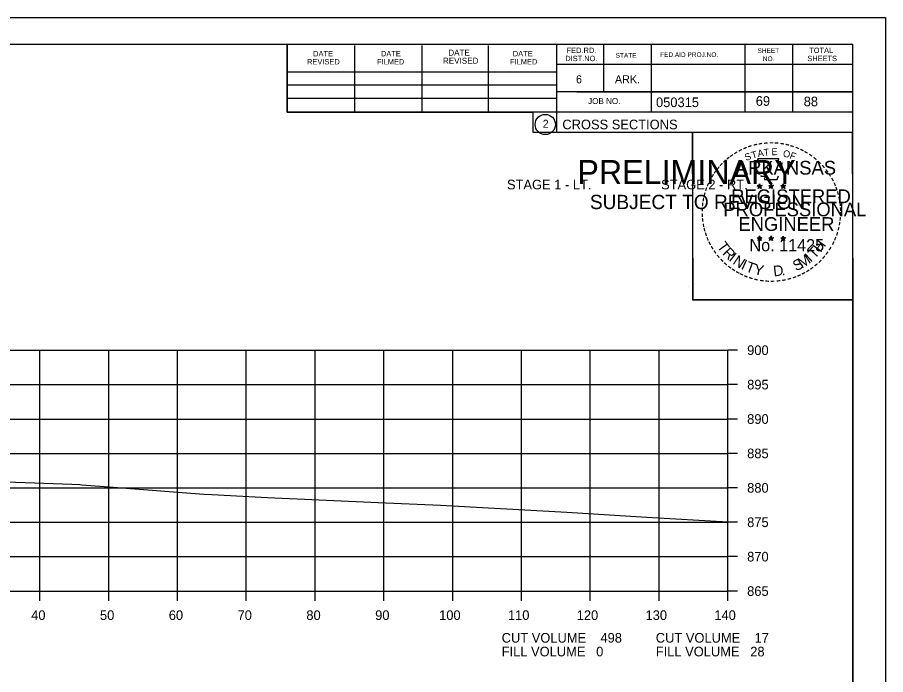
# Model space of a CAD drawing. Extents: x 1486524 to 1499135, y 326561 to 337924.
# Drawn here: x 1489019.6 to 1489145.8, y 332257.1 to 332352.6 of the extents above; entities that cross this region are included whole.
import ezdxf

# ---------------------------------------------------------------- set-up
doc = ezdxf.new("R2010")
doc.units = 0
for name, color, linetype in [('Default', 7, 'Continuous'), ('E_Const Align', 7, 'Continuous'), ('E_Const Align Station', 7, 'Continuous'), ('E_Ownership Information', 7, 'Continuous'), ('E_Property Line', 7, 'Continuous'), ('E_Quarter Calls', 7, 'Continuous'), ('E_Section Line', 7, 'Continuous'), ('E_Station Offset', 7, 'Continuous'), ('E_Tract Number', 7, 'Continuous'), ('S_SIXTEEN_SECTION', 7, 'Continuous')]:
    doc.layers.add(name, color=color, linetype=linetype)

msp = doc.modelspace()

# ---------------------------------------------------------------- linework, layer by layer
at = {"layer": 'E_Const Align'}
for p, q in [((1489122.89, 332269.27), (1489122.89, 332304.27)), ((1489124.29, 332304.27), (1489122.89, 332304.27)), ((1489124.29, 332299.27), (1489122.89, 332299.27)), ((1489124.29, 332294.27), (1489122.89, 332294.27)), ((1489124.29, 332289.27), (1489122.89, 332289.27)), ((1489124.29, 332284.27), (1489122.89, 332284.27)), ((1489124.29, 332279.27), (1489122.89, 332279.27)), ((1489124.29, 332274.27), (1489122.89, 332274.27)), ((1488842.89, 332269.27), (1489122.89, 332269.27)), ((1489022.89, 332267.87), (1489022.89, 332269.27)), ((1489032.89, 332267.87), (1489032.89, 332269.27)), ((1489042.89, 332267.87), (1489042.89, 332269.27)), ((1489052.89, 332267.87), (1489052.89, 332269.27)), ((1489062.89, 332267.87), (1489062.89, 332269.27)), ((1489072.89, 332267.87), (1489072.89, 332269.27)), ((1489082.89, 332267.87), (1489082.89, 332269.27)), ((1489092.89, 332267.87), (1489092.89, 332269.27)), ((1489102.89, 332267.87), (1489102.89, 332269.27)), ((1489112.89, 332267.87), (1489112.89, 332269.27)), ((1489122.89, 332267.87), (1489122.89, 332269.27)), ((1489124.29, 332269.27), (1489122.89, 332269.27))]:
    msp.add_line(p, q, dxfattribs=at)
at = {"layer": 'E_Ownership Information'}
for p, q in [((1488842.89, 332304.27), (1489122.89, 332304.27)), ((1489022.89, 332269.27), (1489022.89, 332304.27)), ((1489032.89, 332269.27), (1489032.89, 332304.27)), ((1489042.89, 332269.27), (1489042.89, 332304.27)), ((1489052.89, 332269.27), (1489052.89, 332304.27)), ((1489062.89, 332269.27), (1489062.89, 332304.27)), ((1489072.89, 332269.27), (1489072.89, 332304.27)), ((1489082.89, 332269.27), (1489082.89, 332304.27)), ((1489092.89, 332269.27), (1489092.89, 332304.27)), ((1489102.89, 332269.27), (1489102.89, 332304.27)), ((1489112.89, 332269.27), (1489112.89, 332304.27)), ((1489122.89, 332269.27), (1489122.89, 332304.27)), ((1488842.89, 332299.27), (1489122.89, 332299.27)), ((1488842.89, 332294.27), (1489122.89, 332294.27)), ((1488842.89, 332289.27), (1489122.89, 332289.27)), ((1488842.89, 332284.27), (1489122.89, 332284.27)), ((1488842.89, 332279.27), (1489122.89, 332279.27)), ((1488842.89, 332274.27), (1489122.89, 332274.27)), ((1488842.89, 332269.27), (1489122.89, 332269.27))]:
    msp.add_line(p, q, dxfattribs=at)
at = {"layer": 'E_Property Line'}
for p, q in [((1488824.89, 332348.73), (1489141.07, 332348.73)), ((1489058.81, 332338.85), (1489058.81, 332348.73)), ((1489068.67, 332338.85), (1489068.67, 332348.53)), ((1489078.43, 332338.85), (1489078.43, 332348.53)), ((1489088.11, 332338.85), (1489088.11, 332348.53)), ((1489097.97, 332348.73), (1489097.97, 332335.93)), ((1489104.81, 332348.73), (1489104.81, 332341.79)), ((1489111.75, 332348.73), (1489111.75, 332338.85)), ((1489125.33, 332348.73), (1489125.33, 332338.85)), ((1489132.27, 332348.73), (1489132.27, 332338.85)), ((1489141.07, 332143.27), (1489141.07, 332348.73)), ((1489141.07, 332345.79), (1489097.97, 332345.79)), ((1489141.07, 332345.81), (1489141.07, 332345.81)), ((1489058.81, 332344.71), (1489097.97, 332344.71)), ((1489058.81, 332342.85), (1489097.97, 332342.85)), ((1489141.07, 332341.79), (1489097.97, 332341.79)), ((1489100.93, 332341.79), (1489141.07, 332341.79)), ((1489058.81, 332338.85), (1489058.81, 332340.91)), ((1489058.81, 332340.91), (1489097.97, 332340.91)), ((1489141.07, 332338.85), (1489058.81, 332338.85)), ((1489097.97, 332335.93), (1489141.07, 332335.93))]:
    msp.add_line(p, q, dxfattribs=at)
msp.add_circle((1489096.35, 332337.07), 1.47, dxfattribs=at)
at = {"layer": 'E_Quarter Calls'}
for p, q in [((1488812.48, 332352.63), (1489145.82, 332352.63)), ((1489117.1, 332313.48), (1489117.1, 332313.48))]:
    msp.add_line(p, q, dxfattribs=at)
for points in [[(1488812.48, 332352.63), (1489145.82, 332352.63), (1489145.82, 332139.29), (1488812.48, 332139.29)], [(1489058.81, 332348.73), (1489058.81, 332338.85), (1489094.54, 332338.85), (1489094.54, 332335.93), (1489117.74, 332335.93), (1489117.74, 332311.6), (1489141.07, 332311.6), (1489141.07, 332143.27), (1488824.89, 332143.27), (1488824.89, 332348.73)], [(1489117.74, 332335.93), (1489140.94, 332335.93), (1489141.07, 332311.6), (1489117.86, 332311.6)]]:
    msp.add_lwpolyline(points, close=True, dxfattribs=at)
at = {"layer": 'E_Tract Number'}
msp.add_lwpolyline([(1489012.5, 332285.34), (1489027.53, 332284.8), (1489028.71, 332284.75), (1489029, 332284.73), (1489033.53, 332284.37), (1489046.73, 332283.35), (1489047.88, 332283.29), (1489055.96, 332282.85), (1489072.04, 332282.14), (1489081.1, 332281.75), (1489099.47, 332280.72), (1489111.1, 332280.03), (1489122.89, 332279.32)], dxfattribs=at)
at = {"layer": 'S_SIXTEEN_SECTION'}
for p, q in [((1489127.15, 332328.19), (1489127.5, 332328.08)), ((1489127.15, 332328.19), (1489127.4, 332328.15)), ((1489127.15, 332328.19), (1489127.39, 332328.07)), ((1489127.28, 332327.78), (1489127.5, 332328.08)), ((1489127.28, 332327.78), (1489127.41, 332328.03)), ((1489127.28, 332327.78), (1489127.5, 332328)), ((1489127.5, 332328.44), (1489127.46, 332328.19)), ((1489127.5, 332328.08), (1489127.5, 332328.44)), ((1489127.5, 332328.44), (1489127.55, 332328.19)), ((1489127.85, 332328.19), (1489127.5, 332328.08)), ((1489127.71, 332327.78), (1489127.5, 332328.08)), ((1489127.71, 332327.78), (1489127.5, 332328)), ((1489127.85, 332328.19), (1489127.56, 332328.14)), ((1489127.71, 332327.78), (1489127.58, 332328.07)), ((1489127.85, 332328.19), (1489127.64, 332328.09)), ((1489128.82, 332328.19), (1489129.17, 332328.08)), ((1489128.82, 332328.19), (1489129.07, 332328.15)), ((1489128.82, 332328.19), (1489129.06, 332328.07)), ((1489128.95, 332327.78), (1489129.17, 332328.08)), ((1489128.95, 332327.78), (1489129.08, 332328.03)), ((1489128.95, 332327.78), (1489129.17, 332328)), ((1489129.17, 332328.44), (1489129.13, 332328.19)), ((1489129.17, 332328.08), (1489129.17, 332328.44)), ((1489129.17, 332328.44), (1489129.22, 332328.19)), ((1489129.52, 332328.19), (1489129.17, 332328.08)), ((1489129.38, 332327.78), (1489129.17, 332328.08)), ((1489129.38, 332327.78), (1489129.17, 332328)), ((1489129.52, 332328.19), (1489129.23, 332328.14)), ((1489129.38, 332327.78), (1489129.25, 332328.07)), ((1489129.52, 332328.19), (1489129.31, 332328.09)), ((1489130.58, 332328.18), (1489130.93, 332328.07)), ((1489130.58, 332328.18), (1489130.84, 332328.13)), ((1489130.58, 332328.18), (1489130.82, 332328.06)), ((1489130.72, 332327.77), (1489130.93, 332328.07)), ((1489130.72, 332327.77), (1489130.84, 332328.01)), ((1489130.72, 332327.77), (1489130.93, 332327.99)), ((1489130.93, 332328.43), (1489130.89, 332328.18)), ((1489130.93, 332328.07), (1489130.93, 332328.43)), ((1489130.93, 332328.43), (1489130.98, 332328.18)), ((1489131.28, 332328.18), (1489130.93, 332328.07)), ((1489131.15, 332327.77), (1489130.93, 332328.07)), ((1489131.15, 332327.77), (1489130.93, 332327.98)), ((1489131.28, 332328.18), (1489130.99, 332328.13)), ((1489131.15, 332327.77), (1489131.01, 332328.06)), ((1489131.28, 332328.18), (1489131.08, 332328.08)), ((1489127.15, 332320.62), (1489127.5, 332320.51)), ((1489127.15, 332320.62), (1489127.4, 332320.57)), ((1489127.15, 332320.62), (1489127.38, 332320.5)), ((1489127.28, 332320.21), (1489127.5, 332320.51)), ((1489127.28, 332320.21), (1489127.41, 332320.45)), ((1489127.28, 332320.21), (1489127.49, 332320.43)), ((1489127.5, 332320.87), (1489127.45, 332320.62)), ((1489127.71, 332320.21), (1489127.49, 332320.42)), ((1489127.5, 332320.51), (1489127.5, 332320.87)), ((1489127.5, 332320.87), (1489127.54, 332320.62)), ((1489127.84, 332320.62), (1489127.5, 332320.51)), ((1489127.71, 332320.21), (1489127.5, 332320.51)), ((1489127.84, 332320.62), (1489127.56, 332320.57)), ((1489127.71, 332320.21), (1489127.57, 332320.5)), ((1489127.84, 332320.62), (1489127.64, 332320.52)), ((1489128.82, 332320.62), (1489129.16, 332320.51)), ((1489128.82, 332320.62), (1489129.07, 332320.57)), ((1489128.82, 332320.62), (1489129.05, 332320.5)), ((1489128.95, 332320.21), (1489129.16, 332320.51)), ((1489128.95, 332320.21), (1489129.07, 332320.45)), ((1489128.95, 332320.21), (1489129.16, 332320.43)), ((1489129.16, 332320.87), (1489129.12, 332320.62)), ((1489129.16, 332320.51), (1489129.16, 332320.87)), ((1489129.16, 332320.87), (1489129.21, 332320.62)), ((1489129.51, 332320.62), (1489129.16, 332320.51)), ((1489129.38, 332320.21), (1489129.16, 332320.51)), ((1489129.38, 332320.21), (1489129.16, 332320.42)), ((1489129.51, 332320.62), (1489129.23, 332320.57)), ((1489129.38, 332320.21), (1489129.24, 332320.5)), ((1489129.51, 332320.62), (1489129.31, 332320.52)), ((1489130.58, 332320.61), (1489130.93, 332320.5)), ((1489130.58, 332320.61), (1489130.84, 332320.56)), ((1489130.58, 332320.61), (1489130.82, 332320.49)), ((1489130.72, 332320.2), (1489130.93, 332320.5)), ((1489130.72, 332320.2), (1489130.84, 332320.44)), ((1489130.72, 332320.2), (1489130.93, 332320.42)), ((1489130.93, 332320.86), (1489130.89, 332320.61)), ((1489130.93, 332320.5), (1489130.93, 332320.86)), ((1489130.93, 332320.86), (1489130.98, 332320.61)), ((1489131.28, 332320.61), (1489130.93, 332320.5)), ((1489131.14, 332320.2), (1489130.93, 332320.5)), ((1489131.14, 332320.2), (1489130.93, 332320.41)), ((1489131.28, 332320.61), (1489130.99, 332320.56)), ((1489131.14, 332320.2), (1489131.01, 332320.49)), ((1489131.28, 332320.61), (1489131.07, 332320.51))]:
    msp.add_line(p, q, dxfattribs=at)
for points in [[(1489127.19, 332332.07), (1489127.46, 332331.24)], [(1489130.7, 332331.15), (1489130.84, 332331.43), (1489130.16, 332331.41), (1489130.31, 332332.07), (1489127.19, 332332.07)], [(1489127.68, 332329.65), (1489127.68, 332329.56), (1489128.25, 332329.54), (1489128.19, 332329.07), (1489130.06, 332329.07), (1489130.26, 332329.6)], [(1489127.5, 332328.44), (1489127.71, 332327.78), (1489127.15, 332328.19), (1489127.85, 332328.19), (1489127.28, 332327.78), (1489127.5, 332328.44)], [(1489129.17, 332328.44), (1489129.38, 332327.78), (1489128.82, 332328.19), (1489129.52, 332328.19), (1489128.95, 332327.78), (1489129.17, 332328.44)], [(1489130.93, 332328.43), (1489131.15, 332327.77), (1489130.58, 332328.18), (1489131.28, 332328.18), (1489130.72, 332327.77), (1489130.93, 332328.43)], [(1489127.5, 332320.87), (1489127.71, 332320.21), (1489127.15, 332320.62), (1489127.84, 332320.62), (1489127.28, 332320.21), (1489127.5, 332320.87)], [(1489129.16, 332320.87), (1489129.38, 332320.21), (1489128.82, 332320.62), (1489129.51, 332320.62), (1489128.95, 332320.21), (1489129.16, 332320.87)], [(1489130.93, 332320.86), (1489131.14, 332320.2), (1489130.58, 332320.61), (1489131.28, 332320.61), (1489130.72, 332320.2), (1489130.93, 332320.86)]]:
    msp.add_lwpolyline(points, dxfattribs=at)
for centre, radius in [((1489127.5, 332328.08), 0.172), ((1489127.5, 332328.08), 0.145), ((1489127.5, 332328.08), 0.116), ((1489127.5, 332328.08), 0.0991), ((1489127.5, 332328.08), 0.0747), ((1489127.5, 332328.08), 0.0495), ((1489127.5, 332328.08), 0.0296), ((1489129.17, 332328.08), 0.172), ((1489129.17, 332328.08), 0.145), ((1489129.17, 332328.08), 0.116), ((1489129.17, 332328.08), 0.0991), ((1489129.17, 332328.08), 0.0747), ((1489129.17, 332328.08), 0.0495), ((1489129.17, 332328.08), 0.0296), ((1489130.93, 332328.07), 0.172), ((1489130.93, 332328.07), 0.145), ((1489130.93, 332328.07), 0.116), ((1489130.93, 332328.07), 0.0991), ((1489130.93, 332328.07), 0.0747), ((1489130.93, 332328.07), 0.0495), ((1489130.93, 332328.07), 0.0296), ((1489127.49, 332320.51), 0.172), ((1489127.49, 332320.51), 0.145), ((1489127.49, 332320.51), 0.116), ((1489127.49, 332320.51), 0.0991), ((1489127.49, 332320.51), 0.0747), ((1489127.49, 332320.51), 0.0495), ((1489127.49, 332320.51), 0.0296), ((1489129.16, 332320.51), 0.172), ((1489129.16, 332320.51), 0.145), ((1489129.16, 332320.51), 0.116), ((1489129.16, 332320.51), 0.0991), ((1489129.16, 332320.51), 0.0747), ((1489129.16, 332320.51), 0.0495), ((1489129.16, 332320.51), 0.0296), ((1489130.93, 332320.5), 0.172), ((1489130.93, 332320.5), 0.145), ((1489130.93, 332320.5), 0.116), ((1489130.93, 332320.5), 0.0991), ((1489130.93, 332320.5), 0.0747), ((1489130.93, 332320.5), 0.0495), ((1489130.93, 332320.5), 0.0296)]:
    msp.add_circle(centre, radius, dxfattribs=at)

# ---------------------------------------------------------------- texts
at = {"layer": 'Default'}
for s, p in [('STAGE 1 - LT.', (1489090.78, 332327.64)), ('STAGE 2 - RT.', (1489113.18, 332327.64))]:
    msp.add_text(s, height=1.4, dxfattribs=at).set_placement(p)
at = {"layer": 'E_Const Align Station'}
for s, p in [('900', (1489125.69, 332303.57)), ('895', (1489125.69, 332298.57)), ('890', (1489125.69, 332293.57)), ('885', (1489125.69, 332288.57)), ('880', (1489125.69, 332283.57)), ('875', (1489125.69, 332278.57)), ('870', (1489125.69, 332273.57)), ('865', (1489125.69, 332268.57)), ('40', (1489021.62, 332265.07)), ('50', (1489031.62, 332265.07)), ('60', (1489041.62, 332265.07)), ('70', (1489051.62, 332265.07)), ('80', (1489061.62, 332265.07)), ('90', (1489071.62, 332265.07)), ('100', (1489080.92, 332265.07)), ('110', (1489090.92, 332265.07)), ('120', (1489100.92, 332265.07)), ('130', (1489110.92, 332265.07)), ('140', (1489120.92, 332265.07)), ('CUT VOLUME    498', (1489090.01, 332261.78)), ('CUT VOLUME    17', (1489112.41, 332261.78)), ('FILL VOLUME   0', (1489090.01, 332259.78)), ('FILL VOLUME   28', (1489112.41, 332259.78))]:
    msp.add_text(s, height=1.4, dxfattribs=at).set_placement(p)
at = {"layer": 'E_Property Line'}
for s, height, p in [('DATE', 0.879, (1489082.25, 332347.07)), ('FED.RD.', 0.782, (1489099.45, 332347.45)), ('SHEET', 0.684, (1489127.19, 332347.45)), ('TOTAL', 0.782, (1489134.71, 332347.45)), ('REVISED', 0.782, (1489061.73, 332345.79)), ('DATE', 0.782, (1489062.61, 332346.97)), ('FILMED', 0.782, (1489071.89, 332345.79)), ('DATE', 0.782, (1489072.47, 332346.97)), ('REVISED', 0.879, (1489081.47, 332345.89)), ('FILMED', 0.782, (1489091.23, 332345.79)), ('DATE', 0.782, (1489091.63, 332346.97)), ('DIST.NO.', 0.782, (1489099.25, 332346.27)), ('STATE', 0.684, (1489106.57, 332346.77)), ('FED.AID PROJ.NO.', 0.684, (1489113.03, 332346.87)), ('NO.', 0.684, (1489127.97, 332346.27)), ('SHEETS', 0.782, (1489134.43, 332346.27)), ('6', 1.17, (1489100.81, 332343.05)), ('ARK.', 1.172, (1489106.47, 332343.05)), ('JOB NO.', 0.879, (1489102.57, 332340.03)), ('050315', 1.4, (1489112.44, 332339.59)), ('2', 1.17, (1489095.97, 332336.58)), ('CROSS SECTIONS', 1.4, (1489098.83, 332336.37))]:
    msp.add_text(s, height=height, rotation=360, dxfattribs=at).set_placement(p)
at = {"layer": 'E_Section Line'}
for s, height, p in [('PRELIMINARY', 3.5, (1489101.02, 332328.4)), ('DWB', 0.01, (1489101.76, 332330.25)), ('SUBJECT TO REVISION', 2.0751, (1489102.83, 332324.77))]:
    msp.add_text(s, height=height, rotation=360, dxfattribs=at).set_placement(p)
at = {"layer": 'E_Station Offset'}
for s, p in [('69', (1489126.94, 332339.78)), ('88', (1489133.91, 332339.71))]:
    msp.add_text(s, height=1.4, dxfattribs=at).set_placement(p)
at = {"layer": 'S_SIXTEEN_SECTION'}
for s, height, rotation, p in [('-', 1.6, 19.1761, (1489125.94, 332333.2)), ('-', 1.6, 13.6301, (1489126.69, 332333.44)), ('-', 1.6, 10.2193, (1489127.37, 332333.6)), ('-', 1.6, 5.8968, (1489128.1, 332333.71)), ('-', 1.6, 0.1862, (1489128.87, 332333.78)), ('-', 1.6, 357.743, (1489129.59, 332333.77)), ('-', 1.6, 352.1617, (1489130.34, 332333.71)), ('-', 1.6, 347.2049, (1489131.05, 332333.6)), ('-', 1.6, 342.3362, (1489131.69, 332333.44)), ('-', 1.6, 36.2317, (1489123.5, 332331.84)), ('-', 1.6, 34.0636, (1489124.08, 332332.24)), ('-', 1.6, 28.7918, (1489124.67, 332332.61)), ('-', 1.6, 24.3072, (1489125.31, 332332.93)), ('S', 1, 21.594, (1489125.55, 332331.75)), ('T', 1, 16.4036, (1489126.46, 332332.08)), ('A', 1, 11.2132, (1489127.29, 332332.33)), ('T', 1, 6.0228, (1489128.14, 332332.49)), ('E', 1, 0.8323, (1489129.24, 332332.6)), ('O', 1, 350.4515, (1489130.84, 332332.39)), ('F', 1, 340.0707, (1489131.8, 332332.17)), ('-', 1.6, 337.8551, (1489132.42, 332333.22)), ('-', 1.6, 334.1211, (1489133.06, 332332.95)), ('-', 1.6, 329.6409, (1489133.63, 332332.67)), ('-', 1.6, 325.8627, (1489134.28, 332332.3)), ('-', 1.6, 48.423, (1489122.14, 332330.57)), ('-', 1.6, 42.9622, (1489122.59, 332331.05)), ('-', 1.6, 38.9507, (1489123.02, 332331.47)), ('ARKANSAS', 2, 360, (1489124.04, 332329.78)), ('-', 1.6, 320.5297, (1489134.89, 332331.88)), ('-', 1.6, 315.5786, (1489135.49, 332331.39)), ('-', 1.6, 54.2325, (1489121.32, 332329.52)), ('-', 1.6, 50.6142, (1489121.74, 332330.09)), ('-', 1.6, 309.8797, (1489136.06, 332330.84)), ('-', 1.6, 306.6522, (1489136.58, 332330.24)), ('-', 1.6, 62.8713, (1489120.69, 332328.38)), ('-', 1.6, 58.0706, (1489121, 332328.99)), ('-', 1.4, 303.6753, (1489137.07, 332329.67)), ('-', 1.6, 299.6684, (1489137.39, 332329.06)), ('-', 1.6, 72.3945, (1489120.21, 332327.14)), ('-', 1.6, 67.7743, (1489120.43, 332327.77)), ('REGISTERED', 2, 360, (1489123.37, 332325.63)), ('DWB', 0.01, 360, (1489127.49, 332328.07)), ('DWB', 0.01, 360, (1489129.16, 332328.07)), ('DWB', 0.01, 360, (1489130.92, 332328.06)), ('-', 1.6, 294.6628, (1489137.71, 332328.45)), ('-', 1.6, 290.5728, (1489137.97, 332327.87)), ('-', 1.6, 81.2013, (1489119.88, 332325.71)), ('-', 1.6, 75.461, (1489120.01, 332326.42)), ('-', 1.6, 285.1233, (1489138.2, 332327.29)), ('-', 1.6, 280.5493, (1489138.4, 332326.55)), ('-', 1.6, 85.1863, (1489119.8, 332325.02)), ('PROFESSIONAL', 2, 360, (1489122.22, 332323.73)), ('-', 1.6, 276.5962, (1489138.56, 332325.78)), ('-', 1.6, 94.1959, (1489119.81, 332323.59)), ('-', 1.6, 89.0622, (1489119.78, 332324.32)), ('-', 1.6, 274.3301, (1489138.62, 332325.06)), ('-', 1.6, 269.9407, (1489138.66, 332324.43)), ('-', 1.6, 98.9479, (1489119.89, 332322.93)), ('-', 1.6, 101.7149, (1489120.02, 332322.19)), ('ENGINEER', 2, 360, (1489124.41, 332321.6)), ('-', 1.6, 260.9953, (1489138.57, 332323.11)), ('-', 1.6, 263.5172, (1489138.64, 332323.76)), ('-', 1.6, 105.4578, (1489120.18, 332321.6)), ('-', 1.6, 109.0874, (1489120.4, 332320.97)), ('-', 1.6, 252.8681, (1489138.28, 332321.71)), ('-', 1.6, 255.7626, (1489138.46, 332322.43)), ('-', 1.6, 114.0643, (1489120.65, 332320.37)), ('-', 1.6, 115.7289, (1489120.96, 332319.75)), ('T', 1.54, 306.0406, (1489121.25, 332319.34)), ('No. 11425', 1.757, 360, (1489126.03, 332318.65)), ('DWB', 0.01, 360, (1489127.48, 332320.5)), ('DWB', 0.01, 360, (1489129.15, 332320.5)), ('DWB', 0.01, 360, (1489130.92, 332320.49)), ('H', 1.54, 54.6088, (1489136.38, 332318.38)), ('-', 1.6, 244.6197, (1489137.79, 332320.41)), ('-', 1.6, 247.8887, (1489138.05, 332321.04)), ('-', 1.6, 120.4471, (1489121.31, 332319.17)), ('-', 1.6, 125.8934, (1489121.72, 332318.61)), ('R', 1.54, 314.005, (1489122.02, 332318.3)), ('T', 1.54, 46.6444, (1489135.49, 332317.44)), ('-', 1.6, 239.0712, (1489137.4, 332319.66)), ('-', 1.6, 130.7181, (1489122.18, 332318.05)), ('-', 1.6, 134.2238, (1489122.7, 332317.51)), ('I', 1.54, 321.9694, (1489122.92, 332317.36)), ('N', 1.54, 326.5002, (1489123.49, 332316.89)), ('S', 1.54, 26.9312, (1489132.8, 332315.71)), ('M', 1.54, 32.6563, (1489133.64, 332316.11)), ('I', 1.54, 42.1136, (1489134.92, 332316.96)), ('-', 1.6, 231.2538, (1489136.56, 332318.44)), ('-', 1.6, 233.8452, (1489136.99, 332319.01)), ('-', 1.6, 138.9338, (1489123.22, 332317.04)), ('-', 1.6, 144.6463, (1489123.78, 332316.64)), ('I', 1.54, 335.3603, (1489124.69, 332316.11)), ('T', 1.54, 339.8912, (1489125.35, 332315.78)), ('Y', 1.54, 347.8556, (1489126.57, 332315.33)), ('D', 1.54, 6.3969, (1489129.56, 332314.98)), ('-', 1.6, 215.7363, (1489135.01, 332316.89)), ('-', 1.6, 221.0851, (1489135.56, 332317.37)), ('-', 1.6, 225.7653, (1489136.09, 332317.88)), ('-', 1.6, 148.0898, (1489124.34, 332316.27)), ('-', 1.6, 151.5704, (1489124.92, 332315.94)), ('-', 1.6, 154.6002, (1489125.44, 332315.7)), ('-', 1.6, 158.5612, (1489126.06, 332315.44)), ('.', 1.54, 13.7642, (1489130.75, 332315.1)), ('-', 1.6, 200.7184, (1489132.68, 332315.57)), ('-', 1.6, 204.2516, (1489133.3, 332315.84)), ('-', 1.6, 207.3568, (1489133.92, 332316.16)), ('-', 1.6, 212.2491, (1489134.48, 332316.51)), ('-', 1.6, 162.7983, (1489126.75, 332315.23)), ('-', 1.6, 167.5555, (1489127.46, 332315.06)), ('-', 1.6, 173.1155, (1489128.24, 332314.95)), ('-', 1.6, 176.5183, (1489128.98, 332314.9)), ('-', 1.6, 181.5918, (1489129.73, 332314.92)), ('-', 1.6, 185.8167, (1489130.54, 332315)), ('-', 1.6, 191.2858, (1489131.27, 332315.13)), ('-', 1.6, 195.4743, (1489132, 332315.33))]:
    msp.add_text(s, height=height, rotation=rotation, dxfattribs=at).set_placement(p)

doc.saveas('drawing.dxf')
